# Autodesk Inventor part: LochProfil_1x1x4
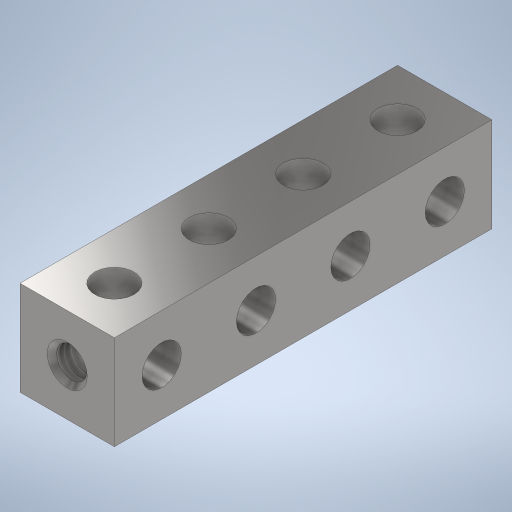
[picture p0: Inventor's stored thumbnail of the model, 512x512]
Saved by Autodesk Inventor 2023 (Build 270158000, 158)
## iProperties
Created: 2023-11
Part Number: LochProfil_1x1x4
Material: Edelstahl
Document SubType Name: Modeling
Designer: Greiner
Density: 8 g/cm^3
Appearance: Halbpoliert
Radius: 2,075 mm
Einheitsmaß: 10,000 mm
Author: Greiner
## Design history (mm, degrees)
sketch "Skizze1"
  geometry: L1 (5, 20)-(-5, 20); L2 (-5, 20)-(-5, -20); L3 (-5, -20)-(5, -20); L4 (5, -20)-(5, 20); 3 further points
  constraints: 8 end point, 2 midpoint, 2 parallel, 1 horizontal, 1 horizontal alignment, 1 perpendicular, 1 vertical alignment
  dimensions: "d0" = 40 distance of L3.end L1.start (computed from Löcher, Einheitsmaß); "d1" = 10 distance of L1.start L1.end (= Einheitsmaß)
extrude "Extrusion1" new body sketch "Skizze1" stored distance "d2" = 10 (= Einheitsmaß); taper "d3" = 0 deg
sketch "Skizze2"
  geometry: C1 r 2.075 at (0, -15); 1 further point
  constraints: 1 centre point, 1 vertical alignment
  dimensions: "d4" = 4.15 diameter of C1 (= 2 x Radius); "d5" = 15 distance of point (0, 0) C1.centre (computed from Löcher, Einheitsmaß)
sketch "Skizze4"
  geometry: C1 r 2.075 at (-35, 5); 1 further point
  constraints: 1 centre point, 1 horizontal alignment
  dimensions: "d6" = 4.15 diameter of C1 (= 2 x Radius); "d7" = 15 distance of point (-20, 5) C1.centre (computed from Löcher, Einheitsmaß)
extrude "Extrusion2" cut sketch "Skizze2" distance "d8" = 10 (= Einheitsmaß); taper "d9" = 0 deg
extrude "Extrusion3" cut sketch "Skizze4" distance "d10" = 10 (= Einheitsmaß); taper "d11" = 0 deg
pattern_linear "Rechteckige Anordnung1" dims "d14" = 10 (= Einheitsmaß)
sketch "Skizze5"
  geometry: 2 further points
  constraints: 1 coincident
hole "Bohrung1" sketch "Skizze5" at (5, -5) diameter "d15" = 3.242; stored, may be unused: countersink angle "d19" = 90 deg, drill point angle "d21" = 118 deg; dims "d16" = 5 (= 0.5 x Einheitsmaß), "d17" = 4, "d18" = 2, "d20" = 10.8 (computed from Einheitsmaß)
mirror "Spiegeln1"
chamfer "Fase2" distance "d25" = 0.5 (= Fasen); stored, may be unused: second distance "d26" = 2, angle "d27" = 45 deg
node "Volumenkörper1"
other parameters: "Einheitsmaß" = 10 [user parameter; used in 10 equation terms], "Radius" = 2.075 [user parameter; used in 2 equation terms], "Fasen" = 0.5 [user parameter; used in 1 equation term]
